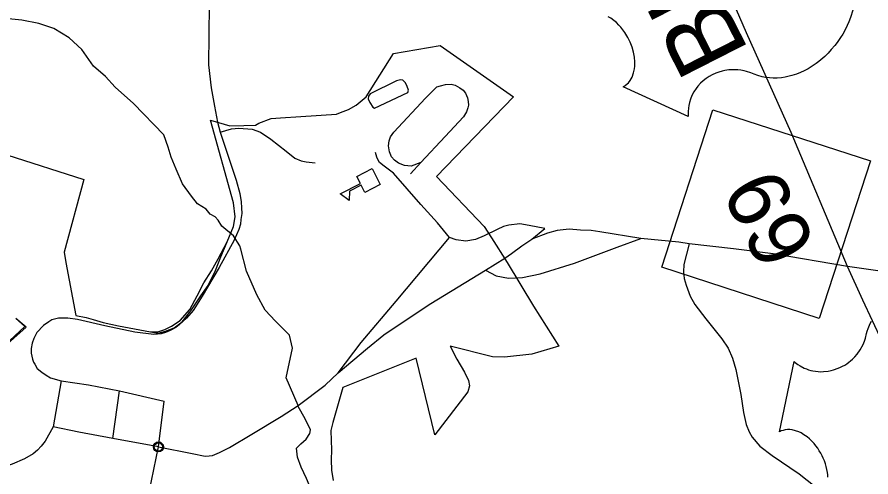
# Model space of a CAD drawing. Extents: x 558484 to 564063, y 513718 to 518374.
# Drawn here: x 559524.5 to 559600.4, y 514909.4 to 514950.3 of the extents above; entities that cross this region are included whole.
import ezdxf

# ---------------------------------------------------------------- set-up
doc = ezdxf.new("R2010")
doc.units = 0
doc.layers.add('Default', color=7, linetype='Continuous')

msp = doc.modelspace()

# ---------------------------------------------------------------- linework, layer by layer
at = {"layer": 'Default'}
for p, q in [((559598.77, 514950.903), (559598.554, 514950.262)), ((559577.266, 514950.188), (559577.022, 514950.331)), ((559577.543, 514949.995), (559577.266, 514950.188)), ((559598.554, 514950.262), (559598.4, 514949.871)), ((559577.765, 514949.805), (559577.543, 514949.995)), ((559577.986, 514949.591), (559577.765, 514949.805)), ((559578.166, 514949.388), (559577.986, 514949.591)), ((559578.519, 514948.934), (559578.166, 514949.388)), ((559598.4, 514949.871), (559598.094, 514949.226)), ((559578.785, 514948.495), (559578.519, 514948.934)), ((559597.857, 514948.791), (559597.671, 514948.493)), ((559598.094, 514949.226), (559597.857, 514948.791)), ((559578.992, 514948.069), (559578.785, 514948.495)), ((559579.163, 514947.618), (559578.992, 514948.069)), ((559597.361, 514948.038), (559597.157, 514947.771)), ((559597.671, 514948.493), (559597.361, 514948.038)), ((559579.283, 514947.187), (559579.163, 514947.618)), ((559579.368, 514946.748), (559579.283, 514947.187)), ((559596.557, 514947.088), (559596.272, 514946.804)), ((559596.849, 514947.403), (559596.557, 514947.088)), ((559597.157, 514947.771), (559596.849, 514947.403)), ((559579.398, 514946.331), (559579.368, 514946.748)), ((559579.39, 514945.946), (559579.398, 514946.331)), ((559595.747, 514946.356), (559595.503, 514946.168)), ((559596.084, 514946.634), (559595.747, 514946.356)), ((559596.272, 514946.804), (559596.084, 514946.634)), ((559579.282, 514945.333), (559579.365, 514945.708)), ((559579.365, 514945.708), (559579.39, 514945.946)), ((559587.401, 514945.556), (559587.165, 514945.5)), ((559587.752, 514945.606), (559587.401, 514945.556)), ((559587.987, 514945.624), (559587.752, 514945.606)), ((559588.316, 514945.621), (559587.987, 514945.624)), ((559588.543, 514945.608), (559588.316, 514945.621)), ((559588.806, 514945.58), (559588.543, 514945.608)), ((559589.1, 514945.527), (559588.806, 514945.58)), ((559594.781, 514945.703), (559594.424, 514945.515)), ((559595.158, 514945.93), (559594.781, 514945.703)), ((559595.503, 514946.168), (559595.158, 514945.93)), ((559578.983, 514944.674), (559579.152, 514944.971)), ((559579.152, 514944.971), (559579.282, 514945.333)), ((559585.724, 514944.839), (559585.46, 514944.632)), ((559586.014, 514945.03), (559585.724, 514944.839)), ((559586.272, 514945.171), (559586.014, 514945.03)), ((559586.596, 514945.32), (559586.272, 514945.171)), ((559586.868, 514945.415), (559586.596, 514945.32)), ((559587.165, 514945.5), (559586.868, 514945.415)), ((559589.32, 514945.47), (559589.1, 514945.527)), ((559589.703, 514945.342), (559589.32, 514945.47)), ((559589.989, 514945.215), (559589.703, 514945.342)), ((559590.335, 514945.094), (559589.989, 514945.215)), ((559590.697, 514944.992), (559590.335, 514945.094)), ((559591.008, 514944.933), (559590.697, 514944.992)), ((559591.36, 514944.891), (559591.008, 514944.933)), ((559591.675, 514944.875), (559591.36, 514944.891)), ((559592.044, 514944.877), (559591.675, 514944.875)), ((559592.414, 514944.909), (559592.044, 514944.877)), ((559592.74, 514944.956), (559592.414, 514944.909)), ((559593.001, 514945.008), (559592.74, 514944.956)), ((559593.354, 514945.099), (559593.001, 514945.008)), ((559593.754, 514945.228), (559593.354, 514945.099)), ((559594.121, 514945.372), (559593.754, 514945.228)), ((559594.424, 514945.515), (559594.121, 514945.372)), ((559578.352, 514944.11), (559578.53, 514944.215)), ((559584.149, 514941.471), (559578.352, 514944.11)), ((559578.53, 514944.215), (559578.725, 514944.371)), ((559578.725, 514944.371), (559578.82, 514944.462)), ((559578.82, 514944.462), (559578.983, 514944.674)), ((559585, 514944.172), (559584.836, 514943.961)), ((559585.238, 514944.432), (559585, 514944.172)), ((559585.46, 514944.632), (559585.238, 514944.432)), ((559584.458, 514943.316), (559584.337, 514943.009)), ((559584.632, 514943.643), (559584.458, 514943.316)), ((559584.836, 514943.961), (559584.632, 514943.643)), ((559584.24, 514942.712), (559584.19, 514942.449)), ((559584.337, 514943.009), (559584.24, 514942.712)), ((559581.783, 514928.07), (559586.335, 514942.065)), ((559584.152, 514942.204), (559584.131, 514941.909)), ((559584.131, 514941.909), (559584.134, 514941.636)), ((559584.19, 514942.449), (559584.152, 514942.204)), ((559586.335, 514942.065), (559600.33, 514937.513)), ((559584.134, 514941.636), (559584.149, 514941.471)), ((559559.481, 514936.357), (559560.389, 514937.37)), ((559600.33, 514937.513), (559595.778, 514923.518)), ((559570.249, 514930.578), (559571.39, 514931.513)), ((559595.778, 514923.518), (559581.783, 514928.07)), ((559600.128, 514922.641), (559600.309, 514923.083)), ((559600.309, 514923.083), (559600.404, 514923.273)), ((559599.897, 514921.777), (559599.988, 514922.169)), ((559599.988, 514922.169), (559600.044, 514922.384)), ((559600.044, 514922.384), (559600.128, 514922.641)), ((559599.676, 514921.199), (559599.801, 514921.497)), ((559599.801, 514921.497), (559599.897, 514921.777)), ((559599.133, 514920.338), (559599.415, 514920.738)), ((559599.415, 514920.738), (559599.676, 514921.199)), ((559598.396, 514919.633), (559598.553, 514919.752)), ((559598.553, 514919.752), (559598.737, 514919.916)), ((559598.737, 514919.916), (559598.944, 514920.12)), ((559598.944, 514920.12), (559599.133, 514920.338)), ((559592.259, 514913.458), (559593.535, 514919.698)), ((559593.535, 514919.698), (559593.628, 514919.614)), ((559593.628, 514919.614), (559593.869, 514919.433)), ((559593.869, 514919.433), (559594.08, 514919.299)), ((559594.08, 514919.299), (559594.45, 514919.103)), ((559594.45, 514919.103), (559594.635, 514919.032)), ((559594.635, 514919.032), (559594.825, 514918.964)), ((559597.041, 514918.946), (559597.463, 514919.096)), ((559597.463, 514919.096), (559597.659, 514919.179)), ((559597.659, 514919.179), (559597.845, 514919.273)), ((559597.845, 514919.273), (559598.037, 514919.384)), ((559598.037, 514919.384), (559598.216, 514919.499)), ((559598.216, 514919.499), (559598.396, 514919.633)), ((559594.825, 514918.964), (559595.018, 514918.91)), ((559595.018, 514918.91), (559595.195, 514918.867)), ((559595.195, 514918.867), (559595.439, 514918.829)), ((559595.439, 514918.829), (559595.676, 514918.805)), ((559595.676, 514918.805), (559595.93, 514918.792)), ((559595.93, 514918.792), (559596.143, 514918.796)), ((559596.143, 514918.796), (559596.569, 514918.842)), ((559596.569, 514918.842), (559596.828, 514918.891)), ((559596.828, 514918.891), (559597.041, 514918.946)), ((559528.448, 514917.988), (559527.73, 514913.893)), ((559533.039, 514912.855), (559533.626, 514917.096)), ((559592.393, 514913.522), (559592.259, 514913.458)), ((559592.559, 514913.579), (559592.393, 514913.522)), ((559592.759, 514913.627), (559592.559, 514913.579)), ((559592.963, 514913.642), (559592.759, 514913.627)), ((559593.162, 514913.647), (559592.963, 514913.642)), ((559593.371, 514913.618), (559593.162, 514913.647)), ((559593.677, 514913.543), (559593.371, 514913.618)), ((559593.954, 514913.44), (559593.677, 514913.543)), ((559594.168, 514913.344), (559593.954, 514913.44)), ((559594.421, 514913.192), (559594.168, 514913.344)), ((559594.705, 514912.99), (559594.421, 514913.192)), ((559594.905, 514912.824), (559594.705, 514912.99)), ((559537.081, 514912.107), (559533.039, 514912.855)), ((559595.115, 514912.627), (559594.905, 514912.824)), ((559595.322, 514912.396), (559595.115, 514912.627)), ((559595.469, 514912.217), (559595.322, 514912.396)), ((559595.639, 514911.986), (559595.469, 514912.217)), ((559595.782, 514911.772), (559595.639, 514911.986)), ((559595.908, 514911.555), (559595.782, 514911.772)), ((559596.034, 514911.315), (559595.908, 514911.555)), ((559596.128, 514911.116), (559596.034, 514911.315)), ((559596.233, 514910.866), (559596.128, 514911.116)), ((559596.319, 514910.612), (559596.233, 514910.866)), ((559596.397, 514910.361), (559596.319, 514910.612)), ((559596.461, 514910.1), (559596.397, 514910.361)), ((559596.507, 514909.84), (559596.461, 514910.1)), ((559596.535, 514909.63), (559596.507, 514909.84)), ((559596.547, 514909.418), (559596.535, 514909.63))]:
    msp.add_line(p, q, dxfattribs=at)
for points in [[(559598.287, 514928.133), (559593.285, 514940.036), (559589.315, 514948.912), (559586.058, 514956.417)], [(559541.581, 514951.391), (559541.527, 514946.059), (559541.761, 514943.997), (559542.049, 514942.38), (559542.328, 514940.957), (559542.568, 514940.066)], [(559549.482, 514915.778), (559548.439, 514918.259), (559548.981, 514920.881), (559548.739, 514922.048), (559547.468, 514923.277), (559546.561, 514924.252), (559545.835, 514925.615), (559544.902, 514927.714), (559544.412, 514929.681), (559544.305, 514929.98), (559543.742, 514930.852), (559542.724, 514931.711), (559542.399, 514932.256), (559542.128, 514932.544), (559541.673, 514932.775), (559541.329, 514933.24), (559540.553, 514933.716), (559540.034, 514934.378), (559539.231, 514935.49), (559538.662, 514936.774), (559538.222, 514937.842), (559537.956, 514938.749), (559537.573, 514939.843), (559534.873, 514942.607), (559533.233, 514944.064), (559532.367, 514945.012), (559531.304, 514945.941), (559530.267, 514947.428), (559529.166, 514948.442), (559527.804, 514949.273), (559526.467, 514949.739), (559524.939, 514950.017), (559522.569, 514950.265)], [(559523.632, 514938.068), (559530.462, 514935.879), (559528.719, 514929.407), (559528.846, 514928.49), (559529.742, 514923.792), (559530.669, 514923.607), (559531.3, 514923.424), (559532.169, 514923.16), (559533.549, 514922.853), (559534.948, 514922.607), (559536.367, 514922.32), (559537.019, 514922.334), (559537.644, 514922.532), (559538.253, 514922.842), (559539.005, 514923.345), (559539.882, 514924.316), (559540.516, 514925.526), (559541.103, 514926.671), (559541.802, 514927.752), (559542.389, 514928.817), (559543.202, 514930.342), (559543.746, 514931.678), (559543.886, 514932.557), (559543.744, 514933.797), (559541.718, 514941.142), (559543.43, 514940.646), (559544.676, 514940.664), (559545.695, 514940.706), (559546.014, 514940.886), (559547.107, 514941.273), (559547.931, 514941.353), (559549.732, 514941.456), (559552.905, 514941.684), (559553.249, 514941.812), (559553.957, 514942.077), (559554.647, 514942.485), (559555.534, 514943.217), (559557.953, 514947.068), (559562.118, 514947.762), (559568.63, 514943.221), (559561.793, 514936.14), (559566.024, 514931.68), (559566.675, 514930.673)], [(559523.632, 514938.068), (559530.462, 514935.879), (559528.719, 514929.407), (559528.846, 514928.49), (559529.742, 514923.792), (559530.669, 514923.607), (559531.3, 514923.424), (559532.169, 514923.16), (559533.549, 514922.853), (559534.948, 514922.607), (559536.367, 514922.32), (559537.056, 514922.217), (559537.701, 514922.393), (559538.48, 514922.689), (559539.197, 514923.206), (559539.963, 514924.201), (559540.86, 514925.516), (559541.51, 514926.452), (559542.152, 514927.788), (559542.62, 514928.985), (559543.202, 514930.342), (559543.746, 514931.678), (559543.886, 514932.557), (559543.744, 514933.797), (559541.718, 514941.142), (559543.43, 514940.646), (559544.676, 514940.664), (559545.695, 514940.706), (559546.014, 514940.886), (559547.107, 514941.273), (559547.931, 514941.353), (559549.732, 514941.456), (559552.905, 514941.684), (559553.249, 514941.812), (559553.957, 514942.077), (559554.647, 514942.485), (559555.534, 514943.217), (559557.953, 514947.068), (559562.118, 514947.762), (559568.63, 514943.221), (559561.793, 514936.14), (559566.024, 514931.68), (559566.675, 514930.673)], [(559523.632, 514938.068), (559530.462, 514935.879), (559528.719, 514929.407), (559528.846, 514928.49), (559529.742, 514923.792), (559530.669, 514923.607), (559531.3, 514923.424), (559532.169, 514923.16), (559533.549, 514922.853), (559534.948, 514922.607), (559536.367, 514922.32), (559537.019, 514922.334), (559537.644, 514922.532), (559538.253, 514922.842), (559539.005, 514923.345), (559539.882, 514924.316), (559540.516, 514925.526), (559541.103, 514926.671), (559541.802, 514927.752), (559542.389, 514928.817), (559543.202, 514930.342), (559543.746, 514931.678), (559543.886, 514932.557), (559543.744, 514933.797), (559541.718, 514941.142), (559543.43, 514940.646), (559544.676, 514940.664), (559545.695, 514940.706), (559546.014, 514940.886), (559547.107, 514941.273), (559547.931, 514941.353), (559549.732, 514941.456), (559552.905, 514941.684), (559553.249, 514941.812), (559553.957, 514942.077), (559554.647, 514942.485), (559555.534, 514943.217), (559557.953, 514947.068), (559562.118, 514947.762), (559568.63, 514943.221), (559561.793, 514936.14), (559566.024, 514931.68), (559566.675, 514930.673)], [(559542.568, 514940.066), (559543.587, 514940.372), (559544.21, 514940.44), (559545.416, 514940.343), (559546.134, 514940.086), (559547.068, 514939.437), (559548.432, 514938.374), (559549.196, 514937.754), (559549.746, 514937.534), (559550.211, 514937.424), (559550.999, 514937.345)], [(559542.568, 514940.066), (559543.991, 514935.804), (559544.304, 514934.63), (559544.43, 514933.894), (559544.462, 514933.341), (559544.48, 514932.852), (559544.412, 514932.32), (559544.359, 514931.902), (559544.213, 514931.419), (559543.809, 514930.466), (559542.468, 514928.033)], [(559562.943, 514930.703), (559561.869, 514932.014), (559560.38, 514933.65), (559557.948, 514936.423), (559557.14, 514937.039), (559556.707, 514937.383), (559556.52, 514937.75), (559556.489, 514937.848), (559556.356, 514938.255)], [(559571.39, 514931.513), (559570.001, 514931.784), (559569.192, 514931.914), (559568.207, 514931.812), (559567.73, 514931.688), (559567.159, 514931.414), (559566.005, 514930.86), (559565.24, 514930.538), (559564.386, 514930.39), (559563.516, 514930.505), (559562.943, 514930.703)], [(559579.928, 514930.618), (559576.289, 514931.209), (559575.513, 514931.34), (559574.564, 514931.372), (559573.552, 514931.458), (559572.5, 514931.347), (559571.632, 514931.106), (559570.249, 514930.578)], [(559566.675, 514930.673), (559568.051, 514928.489), (559570.393, 514924.599), (559572.654, 514921.061), (559570.257, 514920.355), (559567.817, 514920.079), (559566.768, 514920.099), (559562.986, 514921.049), (559563.59, 514919.907), (559564.271, 514918.737), (559564.62, 514918.018), (559564.714, 514917.535), (559564.575, 514917.011), (559561.619, 514913.171), (559559.983, 514919.998), (559553.456, 514917.377), (559552.576, 514914.275), (559552.387, 514913.566), (559552.417, 514912.668), (559552.453, 514911.834), (559552.432, 514910.963), (559552.467, 514910.055), (559552.6, 514909.127)], [(559566.675, 514930.673), (559568.051, 514928.489), (559570.393, 514924.599), (559572.654, 514921.061), (559570.257, 514920.355), (559567.817, 514920.079), (559566.768, 514920.099), (559562.986, 514921.049), (559563.59, 514919.907), (559564.271, 514918.737), (559564.62, 514918.018), (559564.714, 514917.535), (559564.575, 514917.011), (559561.619, 514913.171), (559559.983, 514919.998), (559553.456, 514917.377), (559552.576, 514914.275), (559552.387, 514913.566), (559552.417, 514912.668), (559552.453, 514911.834), (559552.432, 514910.963), (559552.467, 514910.055), (559552.6, 514909.127)], [(559566.675, 514930.673), (559568.051, 514928.489), (559570.393, 514924.599), (559572.654, 514921.061), (559570.257, 514920.355), (559567.817, 514920.079), (559566.768, 514920.099), (559562.986, 514921.049), (559563.59, 514919.907), (559564.271, 514918.737), (559564.62, 514918.018), (559564.714, 514917.535), (559564.575, 514917.011), (559561.619, 514913.171), (559559.983, 514919.998), (559553.456, 514917.377), (559552.576, 514914.275), (559552.387, 514913.566), (559552.417, 514912.668), (559552.453, 514911.834), (559552.432, 514910.963), (559552.467, 514910.055), (559552.6, 514909.127)], [(559553.037, 514918.679), (559555.103, 514921.382), (559558.2, 514925.068), (559562.943, 514930.703)], [(559566.133, 514927.799), (559567.076, 514927.312), (559568.169, 514927.11), (559569.42, 514927.149), (559570.975, 514927.473), (559574.046, 514928.42), (559577.839, 514929.848), (559579.928, 514930.618)], [(559566.133, 514927.799), (559567.837, 514928.867), (559568.45, 514929.285), (559569.371, 514929.978), (559570.249, 514930.578)], [(559584.231, 514930.15), (559583.291, 514930.299), (559579.928, 514930.618)], [(559584.231, 514930.15), (559583.763, 514928.325), (559583.732, 514927.676), (559583.784, 514927.08), (559583.945, 514926.468), (559584.324, 514925.486), (559584.718, 514924.772), (559585.7, 514923.474), (559587.134, 514921.723), (559587.681, 514920.867), (559588.072, 514919.981), (559588.363, 514918.994), (559588.811, 514916.771), (559589.063, 514915.171), (559589.299, 514914.096), (559589.548, 514913.449), (559589.824, 514912.967), (559590.506, 514912.179), (559591.593, 514911.346), (559594.001, 514909.705), (559596.982, 514907.343), (559600.087, 514904.69), (559601.252, 514903.601)], [(559598.287, 514928.133), (559591.67, 514929.259), (559588.154, 514929.706), (559584.231, 514930.15)], [(559607.093, 514896.784), (559606.762, 514899.056), (559606.346, 514902.294), (559606.041, 514905.641), (559605.818, 514907.933), (559605.243, 514912.073), (559604.967, 514913.026), (559604.539, 514914.376), (559604.007, 514915.791), (559602.902, 514918.31), (559601.375, 514921.47), (559599.637, 514925.139), (559598.287, 514928.133)], [(559612.69, 514926.276), (559605.533, 514927.086), (559598.287, 514928.133)], [(559542.468, 514928.033), (559540.965, 514925.498), (559540.165, 514924.238), (559539.575, 514923.546), (559538.929, 514922.946), (559538.622, 514922.71), (559538.138, 514922.455), (559537.717, 514922.285), (559537.332, 514922.151), (559536.673, 514922.082), (559534.993, 514922.289), (559532.315, 514922.855), (559529.884, 514923.43), (559529.047, 514923.555), (559528.685, 514923.549), (559528.194, 514923.535), (559527.614, 514923.399), (559527.342, 514923.234), (559526.873, 514922.88), (559526.284, 514922.273), (559526.007, 514921.75), (559525.854, 514921.316), (559525.776, 514920.859), (559525.79, 514920.43), (559525.887, 514919.889), (559525.992, 514919.631), (559526.1, 514919.455), (559526.326, 514919.081), (559526.736, 514918.747), (559527.099, 514918.47), (559527.488, 514918.232), (559528.448, 514917.988)], [(559553.037, 514918.679), (559555.651, 514920.882), (559557.109, 514922.073), (559559.699, 514923.804), (559561.266, 514924.849), (559566.133, 514927.799)], [(559518.435, 514916.628), (559525.333, 514922.753), (559524.411, 514923.516)], [(559518.535, 514916.597), (559525.209, 514922.817), (559524.411, 514923.516)], [(559518.535, 514916.597), (559525.209, 514922.817), (559524.411, 514923.516)], [(559537.081, 514912.107), (559540.072, 514911.51), (559541.233, 514911.271), (559541.595, 514911.302), (559541.879, 514911.332), (559542.514, 514911.605), (559543.39, 514912.063), (559545.369, 514913.236), (559547.999, 514914.799), (559549.482, 514915.778), (559551.884, 514917.602), (559553.037, 514918.679)], [(559528.448, 514917.988), (559530.863, 514917.632), (559533.626, 514917.096)], [(559533.626, 514917.096), (559537.583, 514916.172)], [(559537.081, 514912.107), (559537.583, 514916.172)], [(559558.132, 514899.548), (559556.377, 514900.648), (559555.358, 514901.324), (559554.055, 514901.942), (559553.068, 514902.392), (559552.373, 514902.801), (559551.709, 514903.293), (559551.549, 514904.04), (559551.394, 514904.928), (559551.18, 514906.028), (559551.039, 514906.887), (559550.771, 514908.031), (559550.241, 514909.299), (559549.757, 514910.313), (559549.434, 514911.194), (559549.359, 514911.981), (559549.729, 514912.383), (559550.196, 514912.796), (559550.527, 514913.284), (559550.585, 514913.618), (559550.139, 514914.546), (559549.459, 514915.743)], [(559527.73, 514913.893), (559527.025, 514912.605), (559526.681, 514912.163), (559526.336, 514911.81), (559525.955, 514911.492), (559525.183, 514911.055), (559524.105, 514910.587), (559522.979, 514910.19), (559520.667, 514909.463)], [(559533.039, 514912.855), (559530.004, 514913.41), (559527.73, 514913.893)], [(559535.445, 514904.908), (559535.834, 514905.908), (559536.454, 514909.095), (559537.081, 514912.107)]]:
    msp.add_lwpolyline(points, dxfattribs=at)
for points in [[(559555.86, 514942.7), (559556.125, 514942.284), (559556.268, 514942.214), (559559.229, 514943.597), (559559.305, 514943.796), (559559.189, 514944.128), (559559.017, 514944.467), (559558.803, 514944.678), (559558.597, 514944.733), (559558.222, 514944.631), (559555.876, 514943.473), (559555.75, 514943.266), (559555.723, 514943.039)], [(559560.389, 514937.37), (559559.533, 514937.059), (559558.944, 514937.097), (559558.418, 514937.327), (559558.062, 514937.572), (559557.797, 514937.882), (559557.603, 514938.334), (559557.514, 514938.858), (559557.568, 514939.312), (559557.693, 514939.66), (559557.988, 514940.059), (559560.817, 514943.099), (559561.816, 514944.106), (559562.142, 514944.2), (559562.574, 514944.296), (559563.07, 514944.335), (559563.446, 514944.26), (559563.852, 514944.022), (559564.144, 514943.797), (559564.351, 514943.53), (559564.538, 514943.127), (559564.597, 514942.802), (559564.621, 514942.476), (559564.552, 514942.227), (559564.441, 514941.886), (559564.175, 514941.431), (559562.549, 514939.696)], [(559556.775, 514935.418), (559555.412, 514934.724), (559555.085, 514935.365), (559554.04, 514934.833), (559554.036, 514934.006), (559553.228, 514934.588), (559555.017, 514935.499), (559554.691, 514936.14), (559556.055, 514936.834)], [(559537.196, 514911.751), (559537.17, 514911.743), (559537.139, 514911.737), (559537.102, 514911.734), (559537.071, 514911.734), (559537.04, 514911.735), (559537.01, 514911.74), (559536.983, 514911.748), (559536.953, 514911.757), (559536.922, 514911.771), (559536.894, 514911.786), (559536.872, 514911.8), (559536.85, 514911.817), (559536.829, 514911.835), (559536.809, 514911.855), (559536.795, 514911.871), (559536.781, 514911.89), (559536.769, 514911.906), (559536.754, 514911.932), (559536.745, 514911.951), (559536.734, 514911.976), (559536.727, 514911.998), (559536.72, 514912.021), (559536.715, 514912.045), (559536.712, 514912.071), (559536.71, 514912.106), (559536.712, 514912.14), (559536.716, 514912.169), (559536.722, 514912.2), (559536.728, 514912.221), (559536.737, 514912.248), (559536.749, 514912.274), (559536.762, 514912.297), (559536.776, 514912.321), (559536.793, 514912.343), (559536.81, 514912.362), (559536.828, 514912.38), (559536.844, 514912.395), (559536.868, 514912.413), (559536.886, 514912.426), (559536.911, 514912.44), (559536.936, 514912.451), (559536.962, 514912.461), (559536.987, 514912.469), (559537.017, 514912.475), (559537.045, 514912.48), (559537.072, 514912.481), (559537.104, 514912.481), (559537.134, 514912.478), (559537.161, 514912.474), (559537.191, 514912.466), (559537.223, 514912.454), (559537.251, 514912.442), (559537.277, 514912.428), (559537.297, 514912.415), (559537.325, 514912.393), (559537.352, 514912.369), (559537.371, 514912.347), (559537.391, 514912.322), (559537.403, 514912.304), (559537.413, 514912.285), (559537.425, 514912.262), (559537.433, 514912.243), (559537.442, 514912.217), (559537.449, 514912.189), (559537.454, 514912.167), (559537.457, 514912.141), (559537.458, 514912.117), (559537.457, 514912.096), (559537.455, 514912.058), (559537.449, 514912.025), (559537.44, 514911.995), (559537.429, 514911.965), (559537.419, 514911.943), (559537.408, 514911.921), (559537.387, 514911.889), (559537.375, 514911.874), (559537.362, 514911.858), (559537.333, 514911.829), (559537.306, 514911.807), (559537.286, 514911.793), (559537.26, 514911.778), (559537.24, 514911.768), (559537.211, 514911.756)]]:
    msp.add_lwpolyline(points, close=True, dxfattribs=at)
for centre, radius in [((559537.081, 514912.107), 0.449), ((559537.081, 514912.106), 0.365)]:
    msp.add_circle(centre, radius, dxfattribs=at)

# ---------------------------------------------------------------- texts
for s, height, p in [('BUS', 6.4453, (559589.59, 514947.252)), ('69', 5.4687, (559595.623, 514930.001))]:
    msp.add_text(s, height=height, rotation=116.98193, dxfattribs=at).set_placement(p)

doc.saveas('drawing.dxf')
